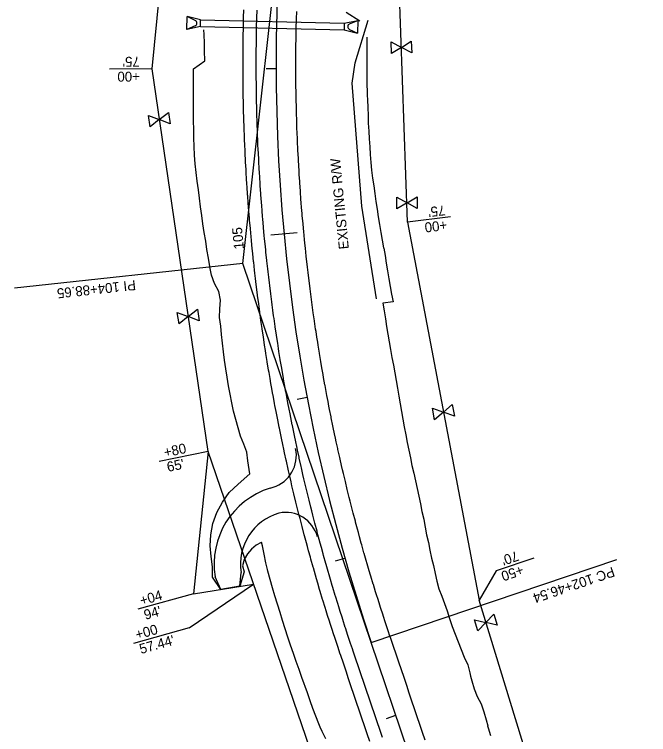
# Model space of a CAD drawing. Extents: x 634057 to 641016, y 287858 to 292331.
# Drawn here: x 634091.5 to 634475.3, y 289064.4 to 289500.2 of the extents above; entities that cross this region are included whole.
import ezdxf

# ---------------------------------------------------------------- set-up
doc = ezdxf.new("R2010")
doc.units = 0
for name, color, linetype in [('53', 7, 'Continuous'), ('PROPOSED SPECIAL DITCHES', 7, 'Continuous'), ('R_50 Horz Alg PC PI PT', 7, 'Continuous'), ('R_50 Horz Alg Stations', 7, 'Continuous'), ('R_50 Horz Alg Ticks', 7, 'Continuous'), ('R_Drive', 7, 'Continuous'), ('R_Horz Alg', 7, 'Continuous'), ('R_No Plot', 7, 'Continuous'), ('R_Proposed Const Limits', 7, 'Continuous'), ('R_Proposed Road', 7, 'Continuous'), ('R_Proposed Shoulder', 7, 'Continuous'), ('R_ROW', 7, 'Continuous'), ('R_Water', 7, 'Continuous')]:
    doc.layers.add(name, color=color, linetype=linetype)

# ---------------------------------------------------------------- blocks, each defined once
blk = doc.blocks.new('FES 48 PLAN AND PROFILE')
at = {"layer": 'R_Water'}
for p, q in [((0, 0), (-1.92, 8.17)), ((0.33, 3.23), (-1.92, 8.17)), ((-1.92, 8.17), (5.92, 8.17)), ((3.66, 3.23), (5.92, 8.17)), ((4, 0), (5.92, 8.17)), ((0, 0), (4, 0))]:
    blk.add_line(p, q, dxfattribs=at)
blk.add_arc((2, 4), 1.83, 204.7144, 335.1272, dxfattribs=at)

msp = doc.modelspace()

# ---------------------------------------------------------------- linework, layer by layer
at = {"layer": '53'}
for p, q in [((634355.31, 289377.61), (634329.31, 289374.55)), ((634208.8, 289235.73), (634179.17, 289229.6)), ((634199.92, 289149.67), (634166.24, 289140.23)), ((634197.21, 289129.02), (634163.53, 289119.58))]:
    msp.add_line(p, q, dxfattribs=at)
for points in [[(634174.82, 289467.18), (634149.04, 289467.12)], [(634405.86, 289171.19), (634383.12, 289163.49), (634372.67, 289145.69)], [(634197.21, 289129.02), (634236.26, 289155.5)]]:
    msp.add_lwpolyline(points, dxfattribs=at)
at = {"layer": 'PROPOSED SPECIAL DITCHES'}
msp.add_lwpolyline([(634310.65, 289328.18), (634301.68, 289384.11), (634295.94, 289458.47), (634297.68, 289470.93), (634305.65, 289496.7)], dxfattribs=at)
at = {"layer": 'R_50 Horz Alg PC PI PT'}
for points in [[(634229.8, 289349.52), (634256.46, 289590.15)], [(634229.8, 289349.52), (634091.45, 289334.52)], [(634307.4, 289120.18), (634229.8, 289349.52)], [(634307.4, 289120.18), (634456.02, 289170.47)]]:
    msp.add_lwpolyline(points, dxfattribs=at)
at = {"layer": 'R_50 Horz Alg Ticks'}
for points in [[(634243.82, 289467.35), (634249.82, 289467.36)], [(634246.68, 289366.76), (634262.61, 289368.26)], [(634262.68, 289267.41), (634268.58, 289268.52)], [(634285.74, 289169.58), (634291.51, 289171.22)], [(634316.64, 289074.18), (634322.32, 289076.1)]]:
    msp.add_lwpolyline(points, dxfattribs=at)
at = {"layer": 'R_Drive'}
msp.add_line((634246.2, 289213.53), (634248.01, 289214.09), dxfattribs=at)
for points in [[(634227.88, 289154.15), (634228.75, 289162.46)], [(634216.45, 289152.32), (634212.97, 289159.87)], [(634227.88, 289154.15), (634216.45, 289152.32)]]:
    msp.add_lwpolyline(points, dxfattribs=at)
for centre, radius, start, end in [((634242.12, 289233.2), 20, 287.1166, 12.4413), ((634260.33, 289167.66), 48, 107.1166, 189.3388), ((634260.33, 289167.66), 32, 105.824, 189.3388), ((634255.61, 289178.85), 20, 15.4298, 101.5467)]:
    msp.add_arc(centre, radius, start, end, dxfattribs=at)
at = {"layer": 'R_Horz Alg'}
msp.add_line((634445.9, 288710.9), (634307.4, 289120.18), dxfattribs=at)
msp.add_arc((635341.17, 289469.99), 1091.35, 173.67885, 198.69496, dxfattribs=at)
at = {"layer": 'R_Proposed Const Limits'}
for points in [[(634206.77, 289472.11), (634206.75, 289472.45), (634206.58, 289477.65), (634206.43, 289482.57), (634206.43, 289482.58), (634206.43, 289482.85), (634206.29, 289488.05), (634206.2, 289490.9)], [(634304.76, 289486.49), (634304.79, 289481.74), (634304.74, 289476.99), (634304.71, 289472.24), (634304.71, 289467.49), (634304.75, 289462.74), (634304.8, 289458), (634304.92, 289453.25), (634305.03, 289451.35), (634305.17, 289448.5), (634305.42, 289443.76), (634305.53, 289439.02), (634305.58, 289434.27), (634305.9, 289429.53), (634306.27, 289424.79), (634306.54, 289420.06), (634306.69, 289415.31), (634307.09, 289410.58), (634307.64, 289405.86), (634308.27, 289401.15), (634308.94, 289396.44), (634309.62, 289391.74), (634310.28, 289387.04), (634310.97, 289382.34), (634311.68, 289377.65), (634312.45, 289372.96), (634313.29, 289368.29), (634314.14, 289363.62), (634314.95, 289358.95), (634314.99, 289358.75), (634315.77, 289354.28), (634316.5, 289349.61), (634317.26, 289344.94), (634318.05, 289340.28), (634318.86, 289335.62), (634319.76, 289330.97), (634320.7, 289326.33), (634314.52, 289325.45), (634315.25, 289320.77), (634316, 289316.08), (634316.76, 289311.39), (634317.54, 289306.71), (634318.36, 289302.03), (634319.17, 289297.35), (634320, 289292.67), (634320.84, 289288), (634321.7, 289283.33), (634322.54, 289278.66), (634323.3, 289273.97), (634324.07, 289269.28), (634324.85, 289264.59), (634325.66, 289259.91), (634326.49, 289255.23), (634327.39, 289250.56), (634328.3, 289245.9), (634329.22, 289241.23), (634330.16, 289236.57), (634331.12, 289231.91), (634332.09, 289227.26), (634333.14, 289222.62), (634334.19, 289217.98), (634335.18, 289213.32), (634336.26, 289208.69), (634337.23, 289204.02), (634338.1, 289199.33), (634339.19, 289194.69), (634339.92, 289190.97), (634340.08, 289190), (634340.94, 289185.29), (634342.09, 289180.67), (634342.96, 289175.95), (634343.94, 289171.27), (634345.18, 289166.66), (634346.07, 289161.94), (634347.07, 289157.26), (634348.44, 289152.68), (634350.12, 289148.21), (634351.82, 289143.74), (634353.42, 289139.24), (634354.89, 289134.63), (634356.46, 289129.88), (634358.32, 289125.23), (634360.04, 289120.54), (634361.84, 289115.86), (634363.75, 289111.23), (634365.92, 289106.69), (634367.05, 289101.79), (634367.46, 289099.82), (634368.28, 289096.93), (634369.66, 289092.12), (634371.5, 289087.46), (634373.9, 289083), (634375.56, 289078.28), (634376.96, 289073.47), (634378.01, 289069.7), (634377.9, 289069.66), (634378.19, 289068.61), (634379.61, 289063.81)], [(634233.86, 289222.16), (634232.7, 289230.07), (634232.21, 289235.27), (634230.26, 289240.17), (634228.29, 289245.08), (634226.81, 289250.09), (634225.43, 289255.12), (634224.09, 289260.16), (634222.97, 289265.26), (634222, 289270.37), (634221.05, 289275.49), (634220.15, 289280.62), (634219.41, 289285.78), (634218.71, 289290.94), (634218.03, 289296.11), (634217.48, 289301.29), (634216.89, 289306.46), (634216.31, 289311.63), (634216.31, 289311.64), (634215.62, 289316.8), (634215.85, 289322.08), (634216.26, 289327.37), (634215.19, 289332.47), (634212.48, 289337.39), (634210.85, 289342.44), (634209.83, 289347.35), (634209.79, 289347.57), (634208.87, 289352.72), (634207.96, 289357.87), (634207.24, 289363.04), (634206.3, 289368.19), (634205.57, 289373.37), (634204.85, 289378.55), (634204.15, 289383.74), (634203.46, 289388.93), (634202.79, 289394.12), (634202.14, 289399.31), (634201.51, 289404.52), (634200.89, 289409.72), (634200.4, 289414.93), (634200.25, 289420.16), (634200.13, 289425.4), (634200.02, 289430.63), (634199.92, 289435.86), (634199.85, 289441.09), (634199.81, 289446.32), (634199.78, 289449.46), (634199.78, 289451.55), (634199.76, 289456.78), (634199.81, 289462.01), (634199.88, 289467.24), (634206.72, 289472.03)], [(634241.07, 289180.87), (634240.78, 289180.75), (634237.8, 289178.97), (634235.03, 289176.62), (634232.55, 289173.73), (634230.43, 289170.37), (634229.45, 289166.59), (634230.53, 289162.86), (634227.88, 289154.15), (634216.45, 289152.32), (634211.27, 289159.76), (634211.29, 289165.96), (634210.63, 289172.16), (634210.01, 289178.66), (634210.29, 289185.38), (634211.52, 289192.17), (634213.95, 289198.73), (634217.34, 289205.01), (634221.54, 289210.97), (634226.85, 289216.02), (634233.86, 289222.16)], [(634280, 289061.78), (634277.81, 289066.32), (634276.45, 289069.02), (634275.74, 289070.9), (634273.9, 289075.55), (634272.14, 289080.24), (634270.47, 289084.95), (634268.79, 289089.66), (634265.41, 289099.07), (634263.72, 289103.78), (634261.98, 289108.62), (634260.3, 289113.56), (634258.66, 289118.51), (634257.02, 289123.46), (634255.39, 289128.41), (634253.8, 289133.38), (634252.23, 289138.35), (634250.68, 289143.33), (634249.14, 289148.32), (634247.64, 289153.31), (634246.17, 289158.32), (634244.83, 289163.36), (634244.56, 289164.4), (634243.67, 289168.45), (634242.57, 289173.55), (634241.54, 289178.67), (634241.07, 289180.87)]]:
    msp.add_lwpolyline(points, dxfattribs=at)
at = {"layer": 'R_Proposed Road'}
for points in [[(634314.16, 289062.78), (634312.55, 289067.52), (634310.95, 289072.25), (634309.35, 289076.99), (634307.75, 289081.73), (634306.14, 289086.46), (634304.54, 289091.2), (634302.94, 289095.93), (634301.34, 289100.67), (634299.73, 289105.41), (634298.13, 289110.14), (634296.53, 289114.88), (634296.03, 289116.34), (634294.92, 289119.65), (634293.91, 289122.68), (634293.32, 289124.45), (634291.82, 289129.04), (634291.75, 289129.25), (634290.2, 289134.07), (634289.77, 289135.41), (634288.67, 289138.88), (634287.76, 289141.79), (634287.17, 289143.71), (634285.79, 289148.18), (634285.68, 289148.54), (634284.22, 289153.38), (634283.86, 289154.59), (634282.78, 289158.23), (634281.97, 289161.01), (634281.37, 289163.08), (634280.11, 289167.43), (634279.97, 289167.94), (634278.6, 289172.8), (634278.3, 289173.87), (634277.25, 289177.67), (634276.52, 289180.33), (634275.92, 289182.55), (634274.79, 289186.79), (634274.61, 289187.44), (634273.33, 289192.32), (634273.09, 289193.26), (634272.07, 289197.22), (634271.43, 289199.74), (634270.83, 289202.12), (634269.81, 289206.23), (634269.62, 289207.03), (634268.42, 289211.94), (634268.23, 289212.73), (634267.25, 289216.86), (634266.69, 289219.24), (634266.1, 289221.78), (634265.19, 289225.77), (634264.98, 289226.71), (634263.87, 289231.64), (634263.73, 289232.29), (634262.79, 289236.58), (634262.31, 289238.83), (634261.73, 289241.52), (634260.93, 289245.38), (634260.7, 289246.47), (634259.69, 289251.42), (634259.58, 289251.93), (634258.7, 289256.38), (634258.28, 289258.5), (634257.73, 289261.34), (634257.02, 289265.07), (634256.78, 289266.31), (634255.86, 289271.28), (634255.8, 289271.65), (634254.96, 289276.25), (634254.61, 289278.23), (634254.09, 289281.23), (634253.47, 289284.82), (634253.23, 289286.21), (634252.4, 289291.2), (634252.37, 289291.42), (634251.6, 289296.19), (634251.3, 289298.03), (634250.81, 289301.18), (634250.28, 289304.64), (634250.05, 289306.18), (634249.31, 289311.18), (634249.3, 289311.26), (634248.59, 289316.18), (634248.36, 289317.88), (634247.9, 289321.19), (634247.45, 289324.51), (634247.23, 289326.2), (634246.59, 289331.15), (634246.58, 289331.21), (634245.96, 289336.23), (634245.77, 289337.79), (634245.36, 289341.25), (634244.99, 289344.43), (634244.78, 289346.27), (634244.25, 289351.08), (634244.22, 289351.3), (634243.69, 289356.32), (634243.55, 289357.74), (634243.18, 289361.35), (634242.89, 289364.39), (634242.7, 289366.38), (634242.27, 289371.06), (634242.23, 289371.42), (634241.79, 289376.45), (634241.69, 289377.72), (634241.38, 289381.49), (634241.15, 289384.39), (634240.98, 289386.53), (634240.65, 289391.06), (634240.61, 289391.57), (634240.26, 289396.62), (634240.19, 289397.74), (634239.94, 289401.66), (634239.77, 289404.42), (634239.64, 289406.71), (634239.39, 289411.1), (634239.36, 289411.75), (634239.1, 289416.8), (634239.06, 289417.78), (634238.87, 289421.85), (634238.76, 289424.46), (634238.66, 289426.9), (634238.5, 289431.15), (634238.48, 289431.95), (634238.31, 289437.01), (634238.29, 289437.84), (634238.17, 289442.06), (634238.11, 289444.52), (634238.06, 289447.11), (634237.98, 289451.21), (634237.96, 289452.17), (634237.89, 289457.22), (634237.89, 289457.9), (634237.85, 289462.28), (634237.83, 289464.59), (634237.82, 289467.33), (634237.82, 289471.28), (634237.82, 289472.39), (634237.85, 289477.44), (634237.85, 289477.98), (634237.89, 289482.5), (634237.92, 289484.67), (634237.96, 289487.55), (634238.03, 289491.36), (634238.05, 289492.6), (634238.17, 289497.66), (634238.18, 289498.04), (634238.31, 289502.71)], [(634340.1, 289061), (634338.49, 289065.74), (634336.89, 289070.47), (634335.29, 289075.21), (634333.69, 289079.95), (634332.08, 289084.68), (634330.48, 289089.42), (634328.88, 289094.15), (634327.27, 289098.89), (634325.67, 289103.63), (634324.07, 289108.36), (634322.47, 289113.1), (634320.86, 289117.84), (634319.26, 289122.57), (634318.77, 289124.03), (634317.68, 289127.27), (634316.69, 289130.24), (634316.12, 289131.97), (634314.65, 289136.45), (634314.58, 289136.67), (634313.06, 289141.37), (634312.64, 289142.68), (634311.57, 289146.09), (634310.68, 289148.93), (634310.09, 289150.81), (634308.75, 289155.18), (634308.64, 289155.53), (634307.21, 289160.27), (634306.86, 289161.45), (634305.81, 289165.01), (634305.01, 289167.73), (634304.42, 289169.76), (634303.19, 289174.02), (634303.05, 289174.51), (634301.71, 289179.27), (634301.42, 289180.32), (634300.39, 289184.03), (634299.68, 289186.63), (634299.09, 289188.8), (634297.98, 289192.95), (634297.81, 289193.58), (634296.56, 289198.36), (634296.32, 289199.28), (634295.32, 289203.15), (634294.7, 289205.62), (634294.11, 289207.95), (634293.11, 289211.97), (634292.92, 289212.75), (634291.76, 289217.55), (634291.57, 289218.33), (634290.61, 289222.36), (634290.06, 289224.7), (634289.49, 289227.18), (634288.59, 289231.08), (634288.39, 289232), (634287.31, 289236.83), (634287.17, 289237.46), (634286.25, 289241.66), (634285.77, 289243.86), (634285.21, 289246.49), (634284.42, 289250.26), (634284.2, 289251.33), (634283.21, 289256.18), (634283.11, 289256.68), (634282.24, 289261.03), (634281.84, 289263.1), (634281.3, 289265.88), (634280.6, 289269.52), (634280.37, 289270.74), (634279.47, 289275.6), (634279.4, 289275.96), (634278.59, 289280.47), (634278.25, 289282.4), (634277.73, 289285.34), (634277.13, 289288.85), (634276.9, 289290.21), (634276.09, 289295.09), (634276.05, 289295.31), (634275.3, 289299.97), (634275.01, 289301.77), (634274.53, 289304.85), (634274.01, 289308.24), (634273.78, 289309.74), (634273.06, 289314.63), (634273.05, 289314.71), (634272.36, 289319.53), (634272.13, 289321.19), (634271.68, 289324.43), (634271.24, 289327.68), (634271.03, 289329.33), (634270.4, 289334.17), (634270.39, 289334.23), (634269.78, 289339.14), (634269.6, 289340.66), (634269.19, 289344.05), (634268.83, 289347.16), (634268.63, 289348.96), (634268.11, 289353.67), (634268.08, 289353.88), (634267.56, 289358.8), (634267.42, 289360.18), (634267.07, 289363.72), (634266.78, 289366.69), (634266.59, 289368.64), (634266.17, 289373.21), (634266.14, 289373.56), (634265.71, 289378.49), (634265.6, 289379.73), (634265.3, 289383.42), (634265.07, 289386.25), (634264.91, 289388.35), (634264.59, 289392.78), (634264.55, 289393.28), (634264.21, 289398.21), (634264.14, 289399.31), (634263.89, 289403.15), (634263.73, 289405.84), (634263.6, 289408.08), (634263.36, 289412.38), (634263.33, 289413.02), (634263.08, 289417.96), (634263.03, 289418.91), (634262.85, 289422.9), (634262.74, 289425.45), (634262.64, 289427.84), (634262.49, 289431.99), (634262.46, 289432.78), (634262.3, 289437.72), (634262.28, 289438.53), (634262.17, 289442.67), (634262.11, 289445.08), (634262.05, 289447.61), (634261.98, 289451.62), (634261.96, 289452.55), (634261.89, 289457.5), (634261.89, 289458.17), (634261.85, 289462.44), (634261.83, 289464.71), (634261.82, 289467.39), (634261.82, 289471.26), (634261.82, 289472.33), (634261.85, 289477.28), (634261.85, 289477.8), (634261.89, 289482.22), (634261.92, 289484.35), (634261.96, 289487.17), (634262.02, 289490.89), (634262.05, 289492.11), (634262.16, 289497.06), (634262.17, 289497.43), (634262.3, 289502)]]:
    msp.add_lwpolyline(points, dxfattribs=at)
at = {"layer": 'R_Proposed Shoulder'}
msp.add_lwpolyline([(634306.58, 289060.22), (634304.98, 289064.95), (634303.37, 289069.69), (634301.77, 289074.43), (634300.17, 289079.16), (634298.57, 289083.9), (634296.96, 289088.63), (634295.36, 289093.37), (634293.76, 289098.11), (634292.16, 289102.84), (634290.55, 289107.58), (634288.95, 289112.32), (634288.46, 289113.77), (634287.33, 289117.11), (634286.32, 289120.16), (634285.73, 289121.94), (634284.21, 289126.57), (634284.14, 289126.78), (634282.58, 289131.63), (634282.15, 289132.98), (634281.04, 289136.48), (634280.13, 289139.41), (634279.53, 289141.34), (634278.14, 289145.85), (634278.03, 289146.21), (634276.56, 289151.09), (634276.2, 289152.3), (634275.11, 289155.97), (634274.29, 289158.77), (634273.68, 289160.85), (634272.42, 289165.24), (634272.28, 289165.75), (634270.89, 289170.65), (634270.59, 289171.73), (634269.53, 289175.55), (634268.8, 289178.22), (634268.2, 289180.47), (634267.05, 289184.73), (634266.88, 289185.39), (634265.59, 289190.31), (634265.34, 289191.25), (634264.32, 289195.24), (634263.67, 289197.78), (634263.07, 289200.18), (634262.04, 289204.32), (634261.85, 289205.12), (634260.64, 289210.07), (634260.45, 289210.87), (634259.46, 289215.02), (634258.9, 289217.43), (634258.31, 289219.98), (634257.39, 289223.99), (634257.17, 289224.94), (634256.06, 289229.91), (634255.92, 289230.57), (634254.97, 289234.89), (634254.48, 289237.16), (634253.91, 289239.87), (634253.09, 289243.75), (634252.86, 289244.85), (634251.84, 289249.84), (634251.74, 289250.35), (634250.85, 289254.83), (634250.43, 289256.96), (634249.87, 289259.83), (634249.16, 289263.58), (634248.92, 289264.83), (634247.99, 289269.84), (634247.93, 289270.21), (634247.09, 289274.85), (634246.73, 289276.84), (634246.21, 289279.86), (634245.58, 289283.48), (634245.35, 289284.88), (634244.51, 289289.9), (634244.47, 289290.13), (634243.7, 289294.93), (634243.4, 289296.78), (634242.9, 289299.96), (634242.37, 289303.44), (634242.14, 289304.99), (634241.39, 289310.03), (634241.38, 289310.11), (634240.67, 289315.07), (634240.43, 289316.78), (634239.97, 289320.11), (634239.52, 289323.46), (634239.3, 289325.16), (634238.65, 289330.14), (634238.65, 289330.21), (634238.02, 289335.26), (634237.83, 289336.83), (634237.41, 289340.32), (634237.04, 289343.52), (634236.83, 289345.37), (634236.29, 289350.22), (634236.27, 289350.44), (634235.73, 289355.5), (634235.59, 289356.92), (634235.22, 289360.56), (634234.92, 289363.63), (634234.73, 289365.63), (634234.3, 289370.34), (634234.26, 289370.7), (634233.82, 289375.78), (634233.71, 289377.05), (634233.4, 289380.85), (634233.17, 289383.77), (634233, 289385.93), (634232.67, 289390.49), (634232.63, 289391), (634232.28, 289396.08), (634232.21, 289397.21), (634231.95, 289401.16), (634231.79, 289403.94), (634231.65, 289406.25), (634231.4, 289410.67), (634231.37, 289411.33), (634231.11, 289416.42), (634231.07, 289417.4), (634230.88, 289421.5), (634230.77, 289424.13), (634230.67, 289426.59), (634230.51, 289430.87), (634230.48, 289431.68), (634230.32, 289436.77), (634230.29, 289437.6), (634230.18, 289441.86), (634230.12, 289444.34), (634230.06, 289446.95), (634229.98, 289451.08), (634229.97, 289452.04), (634229.89, 289457.13), (634229.89, 289457.82), (634229.85, 289462.22), (634229.83, 289464.55), (634229.82, 289467.31), (634229.82, 289471.29), (634229.82, 289472.4), (634229.85, 289477.49), (634229.85, 289478.03), (634229.89, 289482.59), (634229.92, 289484.77), (634229.96, 289487.68), (634230.03, 289491.51), (634230.05, 289492.77), (634230.17, 289497.86), (634230.18, 289498.25), (634230.31, 289502.95)], dxfattribs=at)
at = {"layer": 'R_ROW'}
for p, q in [((634319.45, 289483.58), (634325.68, 289480.24)), ((634319.67, 289476.51), (634319.45, 289483.58)), ((634325.68, 289480.24), (634331.69, 289483.96)), ((634331.69, 289483.96), (634331.91, 289476.9)), ((634325.68, 289480.24), (634319.67, 289476.51)), ((634331.91, 289476.9), (634325.68, 289480.24)), ((634172.58, 289439.05), (634179.17, 289436.49)), ((634173.65, 289432.06), (634172.58, 289439.05)), ((634179.17, 289436.49), (634184.69, 289440.91)), ((634184.69, 289440.91), (634185.76, 289433.92)), ((634179.17, 289436.49), (634173.65, 289432.06)), ((634185.76, 289433.92), (634179.17, 289436.49)), ((634322.9, 289389.55), (634329.08, 289386.11)), ((634323.01, 289382.47), (634322.9, 289389.55)), ((634329.08, 289386.11), (634335.14, 289389.75)), ((634335.14, 289389.75), (634335.25, 289382.67)), ((634329.08, 289386.11), (634323.01, 289382.47)), ((634335.25, 289382.67), (634329.08, 289386.11)), ((634190.07, 289319.91), (634196.66, 289317.34)), ((634191.14, 289312.92), (634190.07, 289319.91)), ((634196.66, 289317.34), (634202.18, 289321.76)), ((634202.18, 289321.76), (634203.25, 289314.77)), ((634196.66, 289317.34), (634191.14, 289312.92)), ((634203.25, 289314.77), (634196.66, 289317.34)), ((634351.11, 289259.49), (634356.5, 289264.06)), ((634356.5, 289264.06), (634357.76, 289257.1)), ((634344.46, 289261.88), (634351.11, 289259.49)), ((634345.71, 289254.92), (634344.46, 289261.88)), ((634351.11, 289259.49), (634345.71, 289254.92)), ((634357.76, 289257.1), (634351.11, 289259.49)), ((634376.77, 289132.28), (634381.67, 289137.38)), ((634381.67, 289137.38), (634383.64, 289130.59)), ((634369.91, 289133.97), (634376.77, 289132.28)), ((634371.88, 289127.18), (634369.91, 289133.97)), ((634376.77, 289132.28), (634371.88, 289127.18)), ((634383.64, 289130.59), (634376.77, 289132.28))]:
    msp.add_line(p, q, dxfattribs=at)
for points in [[(634329.31, 289374.55), (634319.38, 289660.99), (634353.08, 289916.2), (634363.24, 290050.68)], [(634208.8, 289235.73), (634174.82, 289467.18), (634201.66, 289739.35)], [(634329.31, 289374.55), (634372.67, 289145.69)], [(634208.8, 289235.73), (634199.92, 289149.67)], [(634334.33, 288869.02), (634208.8, 289235.73)], [(634199.92, 289149.67), (634236.26, 289155.5)], [(634475.31, 288811.16), (634372.67, 289145.69)]]:
    msp.add_lwpolyline(points, dxfattribs=at)
at = {"layer": 'R_Water'}
for points in [[(634292.29, 289501.46), (634300.48, 289496.19)], [(634204.11, 289496.81), (634291.1, 289494.83)], [(634204.04, 289492.81), (634291.02, 289490.83)]]:
    msp.add_lwpolyline(points, dxfattribs=at)

# ---------------------------------------------------------------- block references
for p, rotation in [((634204.04, 289492.81), 88.936799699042), ((634291.1, 289494.83), -91.21042750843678)]:
    msp.add_blockref('FES 48 PLAN AND PROFILE', p, dxfattribs=dict(at, rotation=rotation))

# ---------------------------------------------------------------- texts
at = {"layer": '53'}
for s, rotation, p in [("75'  ", 180.1382, (634167.36, 289474.53)), ('+00 ', 180.1382, (634167.38, 289465.53)), ('EXISTING R/W', 95.5633, (634293.89, 289358.35)), ("75'", 186.7007, (634351.92, 289384.67)), ('+00 ', 186.7007, (634352.97, 289375.74)), ('+80 ', 11.6882, (634182.57, 289232.16)), ("65'  ", 11.6882, (634184.4, 289223.35)), ("70'  ", 198.695, (634395.51, 289175.66)), ('+50 ', 198.695, (634398.39, 289167.14)), ('+04 ', 15.6534, (634168.35, 289142.5)), ("94'", 15.6534, (634170.78, 289133.83)), ('+00 ', 15.6534, (634165.64, 289121.85)), ("57.44'", 15.6534, (634168.07, 289113.18))]:
    msp.add_text(s, height=6, rotation=rotation, dxfattribs=at).set_placement(p)
at = {"layer": 'R_50 Horz Alg PC PI PT'}
for s, rotation, p in [('PI 104+88.65', 186.1869, (634164.62, 289339.43)), ('PC 102+46.54', 198.695, (634453.51, 289166.04))]:
    msp.add_text(s, height=6, rotation=rotation, dxfattribs=at).set_placement(p)
at = {"layer": 'R_50 Horz Alg Stations'}
msp.add_text('105', height=6, rotation=95.3882, dxfattribs=at).set_placement((634230.4, 289358.33))
at = {"layer": 'R_No Plot'}
for rotation, p in [(104.1011, (634282.76, 289204.07)), (108.695, (634307.46, 289120.16)), (108.695, (634307.46, 289120.16)), (108.695, (634307.46, 289120.16)), (108.695, (634307.46, 289120.16)), (108.695, (634307.46, 289120.16)), (108.695, (634307.46, 289120.16)), (108.695, (634307.46, 289120.16)), (108.695, (634307.46, 289120.16))]:
    msp.add_text('+', height=0.1, rotation=rotation, dxfattribs=at).set_placement(p)

doc.saveas('drawing.dxf')
